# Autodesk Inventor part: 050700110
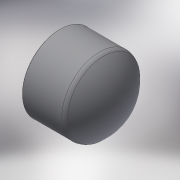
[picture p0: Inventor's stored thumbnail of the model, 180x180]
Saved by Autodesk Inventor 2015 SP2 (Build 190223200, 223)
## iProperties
Created: 2017-10
Part Number: 050700110
Material: Generic
Description: PLASSON CAP-CEMENT PVC 110
Document SubType Name: Modeling
Designer: KIM
Density: 1 g/cm^3
Appearance: Default
Author: KIM
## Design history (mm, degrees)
derived "050700.ipt"
feature "Solid1::050700.ipt"
tag "TaggingFeature1"
body "Solid1"
other parameters: "d7" = 1.1, "d9" = 126, "d28" = 1, "d29" = 61, "d31" = 99, "d32" = 85, "d33" = 64.05, "d34" = 11, "E_" = 126, "H_" = 85, "l_" = 61
